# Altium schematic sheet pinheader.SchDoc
size A
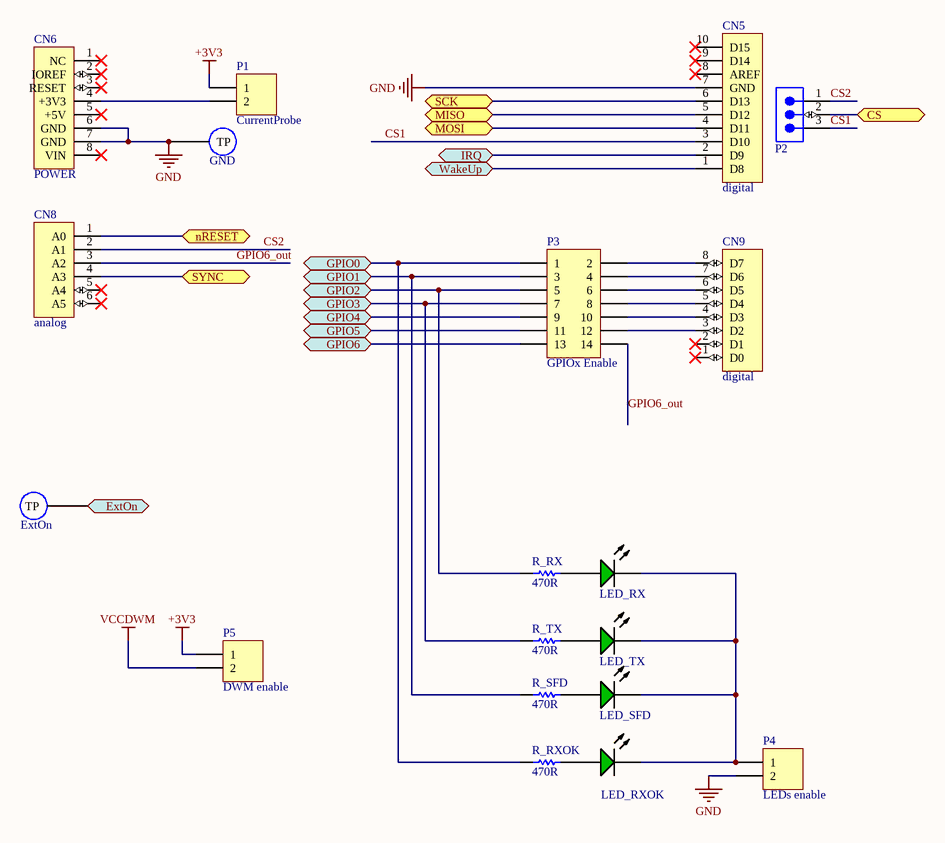
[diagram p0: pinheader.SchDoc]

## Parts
CN5  digital  [HDR1X10]
CN6  POWER  [HDR1X8]
CN8  analog  [HDR1X6]
CN9  digital  [HDR1X8]
ExtOn  Component_1  [KSTN-5000]  (value not drawn)
GND  Component_1  [KSTN-5000]  (value not drawn)
LED_RX  APG1608CGKC/T  [KING-LED0603-25-GREEN_V]  (value not drawn)
LED_RXOK  APG1608CGKC/T  [KING-LED0603-25-GREEN_V]  (value not drawn)
LED_SFD  APG1608CGKC/T  [KING-LED0603-25-GREEN_V]  (value not drawn)
LED_TX  APG1608CGKC/T  [KING-LED0603-25-GREEN_V]  (value not drawn)
P1  CurrentProbe  [HDR1X2H]
P2  Through-hole  [SMTC-MTSW-103-08-X-S-229-RA]  (value not drawn)
P3  GPIOx Enable  [HDR2X7]
P4  LEDs enable  [HDR1X2]
P5  DWM enable  [HDR1X2]
R_RX  470R  [RESC0603(1608)_L]
R_RXOK  470R  [RESC0603(1608)_L]
R_SFD  470R  [RESC0603(1608)_L]
R_TX  470R  [RESC0603(1608)_L]

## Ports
CS (bidir), ExtOn (bidir), GPIO0 (bidir), GPIO1 (bidir), GPIO2 (bidir), GPIO3 (bidir), GPIO4 (bidir), GPIO5 (bidir), GPIO6 (bidir), IRQ (bidir), MISO (bidir), MOSI (bidir), nRESET (bidir), SCK (bidir), SYNC (bidir), WakeUp (bidir)

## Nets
+3V3: P1.1 P5.1
GND: CN5.7(GND) CN6.6(GND) CN6.7(GND) GND.1(TP) P4.2
VCCDWM: P5.2
CS: P2.2 ; port CS
CS1: CN5.3(D10) P2.3
CS2: CN8.2(A1) P2.1
ExtOn: ExtOn.1(TP) ; port ExtOn
GPIO0: P3.1 R_RXOK.1 ; port GPIO0
GPIO1: P3.3 R_SFD.1 ; port GPIO1
GPIO2: P3.5 R_RX.1 ; port GPIO2
GPIO3: P3.7 R_TX.1 ; port GPIO3
GPIO4: P3.9 ; port GPIO4
GPIO5: P3.11 ; port GPIO5
GPIO6: P3.13 ; port GPIO6
GPIO6_out: CN8.3(A2) P3.14
IRQ: CN5.2(D9) ; port IRQ
MISO: CN5.5(D12) ; port MISO
MOSI: CN5.4(D11) ; port MOSI
nRESET: CN8.1(A0) ; port nRESET
SCK: CN5.6(D13) ; port SCK
SYNC: CN8.4(A3) ; port SYNC
WakeUp: CN5.1(D8) ; port WakeUp
NetCN6_4: CN6.4(+3V3) P1.2
NetCN9_3: CN9.3(D2) P3.12
NetCN9_4: CN9.4(D3) P3.10
NetCN9_5: CN9.5(D4) P3.8
NetCN9_6: CN9.6(D5) P3.6
NetCN9_7: CN9.7(D6) P3.4
NetCN9_8: CN9.8(D7) P3.2
NetLED_RX_1: LED_RX.1(A) R_RX.2
NetLED_RX_2: LED_RX.2(K) LED_RXOK.2(K) LED_SFD.2(K) LED_TX.2(K) P4.1
NetLED_RXOK_1: LED_RXOK.1(A) R_RXOK.2
NetLED_SFD_1: LED_SFD.1(A) R_SFD.2
NetLED_TX_1: LED_TX.1(A) R_TX.2

Not connected (* = marked no-connect by the designer): CN5 8(AREF)* 9(D14)* 10(D15)*; CN6 1(NC)* 2(IOREF)* 3(RESET)* 5(+5V)* 8(VIN)*; CN8 5(A4)* 6(A5)*; CN9 1(D0)* 2(D1)*

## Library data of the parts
CN5 = Header 10: Header, 10-Pin
CN6 CN9 = Header 8: Header, 8-Pin
CN8 = Header 6: Header, 6-Pin
ExtOn GND = Component_1: test point
LED_RX LED_RXOK LED_SFD LED_TX = CMP-0239-00001-1: LED, SMT, 0603(1608), 0.25mm Thickness, Green; Forward Current: 30 mA; Reverse Voltage: 5 V; Power Dissipation: 78 mW; Packing: Reel
P1 = Header 2H: Header, 2-Pin, Right Angle
P2 = CMP-1024-00100-1: Modified .025" SQ Post Header, Through-hole, Right Angle, -55 to 125 degC, 2.54 mm Pitch, 3-Pin, Male, RoHS; Manufacturer: Samtec; PartNumber: MTSW-103-08-G-S-229-RA; Pitch: 2.54 mm
P3 = Header 7X2: Header, 7-Pin, Dual row
P4 P5 = Header 2: Header, 2-Pin
R_RX R_RXOK R_SFD R_TX = CMP-1012-00473-1: 470R 0.1W 1% 0603 (1608 Metric)  SMD; Value: 470.00 Ohm; Case-Metric: 1608; Case-EIA: 0603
